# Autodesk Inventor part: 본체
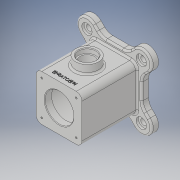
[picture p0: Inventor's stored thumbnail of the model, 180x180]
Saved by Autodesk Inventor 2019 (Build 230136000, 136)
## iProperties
Created: 2021-01
Part Number: 본체
Material: 일반
Document SubType Name: Modeling
Designer: 3dpro23
Density: 1 g/cm^3
Appearance: 기본값
Mass: 385.865 g
Surface Area: 854.376 cm^2
Volume: 385.865 cm^3
Author: 3dpro23
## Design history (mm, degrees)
sketch "스케치1"
  geometry: L1 (-40, -40)-(40, -40); L2 (40, -40)-(40, 40); L3 (40, 40)-(-40, 40); L4 (-40, 40)-(-40, -40); L5 (-40, -40)-(40, 40); L6 (40, -40)-(-40, 40); 1 further point
  constraints: 12 end point, 2 midpoint, 2 parallel, 1 horizontal, 1 perpendicular
  dimensions: "d0" = 80 distance of L3.end L2.end; "d1" = 80 distance of L2.end L1.end
extrude "돌출1" new body sketch "스케치1" distance "d2" = 108; taper "d3" = 0 deg
sketch "스케치2"
  geometry: L1 (40, -40)-(-40, -40) reference; L2 (40, 40)-(40, -40) reference; L3 (-40, 40)-(40, 40) reference; L4 (-40, -40)-(-40, 40) reference; L5 (-48, -48)-(48, -48); L6 (48, -48)-(48, 48); L7 (48, 48)-(-48, 48); L8 (-48, 48)-(-48, -48); L9 (-48, -48)-(48, 48); L10 (48, -48)-(-48, 48); L11 (0, 0)-(47.376, 47.376); L12 (34.648, 60.104)-(14.544, 40); L13 (-40, 40)-(40, 40) reference; L14 (60.104, 34.648)-(40, 14.544); A1 r 18 centre (47.376, 47.376) between (34.648, 60.104) and (60.104, 34.648)
  constraints: 18 end point, 4 parallel, 3 point on line, 2 midpoint, 2 point on circle, 2 tangent, 1 centre point, 1 coincident, 1 horizontal, 1 perpendicular
  dimensions: "d4" = 96 distance of L7.end L6.end; "d5" = 96 distance of L6.end L5.end; "d6" = 67 distance of L11.start L11.end; "d7" = 36 diameter of A1
  node "투영된 루프1"
extrude "돌출2" join sketch "스케치2" distance "d8" = 12; taper "d9" = 0 deg
sketch "스케치3"
  geometry: L1 (-30, -30)-(30, -30); L2 (30, -30)-(30, 30); L3 (30, 30)-(-30, 30); L4 (-30, 30)-(-30, -30); L5 (-30, -30)-(30, 30); L6 (30, -30)-(-30, 30); 5 further points
  constraints: 12 end point, 4 coincident, 2 midpoint, 2 parallel, 1 horizontal, 1 perpendicular
  dimensions: "d13" = 60 distance of L3.end L2.end; "d14" = 60 distance of L2.end L1.end
hole "구멍1" sketch "스케치3" at (-30, 30), (-30, -30), (30, 30), (30, -30) diameter "d15" = 3.242; stored, may be unused: countersink angle "d19" = 90 deg, drill point angle "d21" = 118 deg; dims "d16" = 8, "d17" = 4, "d18" = 2, "d20" = 10
sketch "스케치4"
  geometry: C1 r 25 at (0, 0); 1 further point
  constraints: 1 centre point, 1 coincident
  dimensions: "d22" = 50 diameter of C1
extrude "돌출3" cut sketch "스케치4" distance "d23" = 12; taper "d24" = 0 deg
sketch "스케치5"
  geometry: C1 r 25 at (0, 0) reference; 2 further points
  constraints: 1 coincident
hole "구멍2" sketch "스케치5" at (0, 0) diameter "d25" = 70; stored, may be unused: countersink angle "d29" = 90 deg, drill point angle "d31" = 0 deg; dims "d26" = 8, "d27" = 4, "d28" = 2, "d30" = 84
sketch "스케치6"
  geometry: C1 r 35 at (0, 0) reference; 2 further points
  constraints: 1 coincident
hole "구멍3" sketch "스케치6" at (0, 0) diameter "d32" = 50; stored, may be unused: countersink angle "d36" = 90 deg, drill point angle "d38" = 0 deg; dims "d33" = 8, "d34" = 4, "d35" = 2, "d37" = 12
node "작업 평면1"
sketch "스케치7"
  geometry: L1 (-22.544, 12)-(22.544, 12) reference; C1 r 20 at (0, 59); 1 further point
  constraints: 1 centre point, 1 vertical alignment
  dimensions: "d40" = 40 diameter of C1; "d42" = 47 distance from line of C1.centre L1
extrude "돌출4" join sketch "스케치7" stored distance "d43" = 12; taper "d44" = 0 deg
sketch "스케치8"
  geometry: C1 r 20 at (0, 0) reference; 2 further points
  constraints: 1 coincident
hole "구멍4" sketch "스케치8" at (0, 0) diameter "d45" = 25; stored, may be unused: countersink angle "d49" = 90 deg, drill point angle "d51" = 0 deg; dims "d46" = 8, "d47" = 30, "d48" = 8, "d50" = 34.5
sketch "스케치9"
  geometry: C1 r 67 at (0, 0); C2 r 9 at (-47.376, 47.376); A1 r 18 centre (-47.376, 47.376) between (-34.648, 60.104) and (-60.104, 34.648) reference; 1 further point
  constraints: 2 centre point, 1 coincident, 1 concentric
  dimensions: "d52" = 134 diameter of C1; "d53" = 18 diameter of C2
extrude "돌출5" cut sketch "스케치9" distance "d54" = 4; taper "d55" = 0 deg
sketch "스케치10"
  geometry: C1 r 9 at (0, 0) reference; 2 further points
  constraints: 1 coincident
hole "구멍5" sketch "스케치10" at (0, 0) diameter "d56" = 10; stored, may be unused: countersink angle "d60" = 90 deg, drill point angle "d62" = 0 deg; dims "d57" = 8, "d58" = 4, "d59" = 2, "d61" = 8
sketch "스케치11"
  geometry: L1 (17.456, 108)-(62.544, 108) reference; L2 (80, 0)-(0, 0) reference; 3 further points
  constraints: 1 midpoint, 1 vertical alignment, 1 other
  dimensions: "d66" = 10 distance from line of L2 point (40, 10)
feature "엠보싱1" sketch "스케치11" dims "d0" = 80, "d1" = 80, "d67" = 0.5, "d68" = 0
fillet "모깎기1" dims "d69" = 3
chamfer "모따기1" distance "d70" = 1; stored, may be unused: second distance "d71" = 2, angle "d72" = 45 deg
chamfer "모따기2" distance "d73" = 1; stored, may be unused: second distance "d74" = 2, angle "d75" = 45 deg
chamfer "모따기3" distance "d76" = 1; stored, may be unused: second distance "d77" = 2, angle "d78" = 45 deg
fillet "모깎기2" dims "d79" = 20
fillet "모깎기3" dims "d80" = 3
fillet "모깎기4" dims "d81" = 10
fillet "모깎기5" dims "d82" = 3
sketch "스케치12"
  geometry: L1 (-30, -30)-(30, -30); L2 (30, -30)-(30, 30); L3 (30, 30)-(-30, 30); L4 (-30, 30)-(-30, -30); L5 (-30, -30)-(30, 30); L6 (30, -30)-(-30, 30); C1 r 1.621 at (30, 30) reference; C2 r 1.621 at (-30, 30) reference; C3 r 1.621 at (-30, -30) reference; 5 further points
  constraints: 12 end point, 4 coincident, 2 midpoint, 2 parallel, 1 horizontal, 1 perpendicular
  dimensions: "d83" = 60 distance of L3.end L2.end (derived); "d84" = 60 distance of L2.end L1.end (derived)
hole "구멍6" sketch "스케치12" at (-30, 30), (-30, -30), (30, -30), (30, 30) diameter "d85" = 3.242; stored, may be unused: countersink angle "d89" = 90 deg, drill point angle "d91" = 118 deg; dims "d86" = 8, "d87" = 4, "d88" = 2, "d90" = 10
node "솔리드1"
pattern_circular "원형 패턴1" dims angle "d11" = 360 deg
pattern_circular "원형 패턴2" dims angle "d64" = 360 deg
other parameters: "d39" = 55
